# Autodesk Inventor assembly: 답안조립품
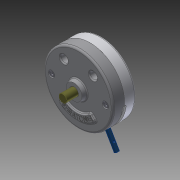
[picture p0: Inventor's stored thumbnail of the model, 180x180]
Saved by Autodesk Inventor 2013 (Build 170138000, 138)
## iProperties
Created: 2015-05
Part Number: 답안조립품
Document SubType Name: Assembly
Designer: Administrator
Author: Administrator
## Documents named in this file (10)
- C:\Users\Administrator\Desktop\Inventor2급\답안조립품.iam
- C:\Users\Administrator\Desktop\Inventor2급\본체.ipt
- C:\Users\Administrator\Desktop\Inventor2급\20150513-2급공용부품\덮개.ipt
- C:\Users\Administrator\Desktop\Inventor2급\20150513-2급공용부품\축.ipt
- C:\Users\Administrator\Desktop\Inventor2급\20150513-2급공용부품\슬라이더2.ipt
- C:\Users\Administrator\Desktop\Inventor2급\20150513-2급공용부품\슬라이더.ipt
- C:\Users\Administrator\Desktop\Inventor2급\20150513-2급공용부품\평행핀.ipt
- C:\Users\Administrator\Desktop\Inventor2급\20150513-2급공용부품\베어링62_22.ipt
- C:\Users\Administrator\Desktop\Inventor2급\20150513-2급공용부품\멈춤링.ipt
- C:\Users\Administrator\Desktop\Inventor2급\20150513-2급공용부품\M 10 x 35.ipt
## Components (2 placed, 1 different names)
1. M 10 x 35:1
2. M 10 x 35:2
